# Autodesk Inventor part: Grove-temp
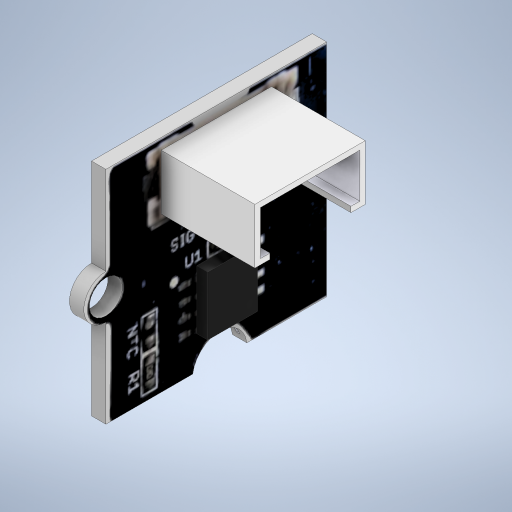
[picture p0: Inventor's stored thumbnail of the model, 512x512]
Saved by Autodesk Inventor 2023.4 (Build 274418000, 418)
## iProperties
Created: 2022-12
Part Number: Grove-temp
Material: Générique
Document SubType Name: Modeling
Designer: ecuenot
Density: 1 g/cm^3
Appearance: Par défaut
Author: ecuenot
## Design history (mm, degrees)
sketch "Esquisse1"
  geometry: L1 (20, 0)-(20, -20); L2 (0, -20)-(0, 0); L3 (11.5, 0)-(12, 0); L4 (10, 0)-(8, 0); L5 (0, 0)-(8, 0); L6 (11.5, 0)-(20, 0); L7 (20, -20)-(12, -20); L8 (8, -20)-(0, -20); C1 r 1.5 at (10, -20); A1 r 2 centre (10, 0) between (12, 0) and (8, 0); A2 r 2 centre (10, -20) between (8, -20) and (12, -20); 2 further points
  constraints: 16 end point, 5 parallel, 4 point on circle, 3 centre point, 2 coincident, 2 horizontal, 2 perpendicular, 1 horizontal alignment, 2 other
  dimensions: "d0" = 20 distance of L1.end L2.start; "d1" = 20 distance of L1.start L1.end
extrude "Extrusion1" new body sketch "Esquisse1" distance "d9" = 1.3; taper "d10" = 0 deg
sketch "Esquisse6"
  geometry: L1 (20, 20)-(0, 20) reference; L2 (15, 14)-(5, 14); L3 (5, 14)-(5, 19); L4 (5, 19)-(15, 19); L5 (15, 19)-(15, 14); L6 (15, 14)-(5, 19); L7 (5, 14)-(15, 19); 2 further points
  constraints: 12 end point, 2 midpoint, 2 parallel, 1 horizontal, 1 perpendicular
  dimensions: "d36" = 10 distance of L3.end L4.end; "d37" = 5 distance of L2.end L3.end
extrude "Extrusion4" join sketch "Esquisse6" distance "d38" = 8.5; taper "d39" = 0 deg
feature "Coque2" dims "d41" = 0.5
sketch "Esquisse7"
  geometry: L1 (3.749, 1.295)-(8.801, 1.295); L2 (8.801, 1.295)-(8.801, 8.634); L3 (8.801, 8.634)-(3.749, 8.634); L4 (3.749, 8.634)-(3.749, 1.295); L5 (3.749, 1.295)-(8.801, 8.634); L6 (8.801, 1.295)-(3.749, 8.634); 1 further point
  constraints: 12 end point, 2 parallel, 1 horizontal, 1 perpendicular
extrude "Extrusion5" cut sketch "Esquisse7" stored distance "d44" = 8.5; taper "d45" = 0 deg
sketch "Esquisse8" dims "d52" = 10
  geometry: L1 (-4.5, 7.064)-(-14.5, 7.064) reference; C1 r 0.5 at (-12.533, 4.536); C2 r 0.5 at (-10.533, 4.536); C3 r 0.5 at (-8.533, 4.536); C4 r 0.5 at (-6.533, 4.536); 1 further point
  constraints: 4 centre point, 1 horizontal, 6 other
  dimensions: "d46" = 1 diameter of C1; "d49" = 2 distance of C1.centre C2.centre
extrude "Extrusion6" join sketch "Esquisse8" distance "d54" = 7; taper "d55" = 0 deg
fillet "Congé2" dims "d56" = 0.5
sketch "Esquisse11"
  geometry: L1 (0, 0)-(20, 0) reference; C1 r 2.474 at (10.322, -0.327); 2 further points
  constraints: 1 centre point
extrude "Extrusion7" cut sketch "Esquisse11" distance "d73" = 7; taper "d74" = 0 deg
sketch "Esquisse12"
  geometry: L1 (12.727, 8.321)-(8.23, 8.321); L2 (8.23, 8.321)-(8.23, 2.989); L3 (8.23, 2.989)-(12.727, 2.989); L4 (12.727, 2.989)-(12.727, 8.321); 1 further point
  constraints: 8 end point, 2 parallel, 1 horizontal, 1 perpendicular
extrude "Extrusion8" join sketch "Esquisse12" distance "d75" = 1; taper "d76" = 0 deg
sketch "Esquisse15"
  geometry: L1 (-17.164, 54.007)-(43.478, 54.007); L2 (43.478, 54.007)-(43.478, -26.803); L3 (43.478, -26.803)-(-17.164, -26.803); L4 (-17.164, -26.803)-(-17.164, 54.007); 1 further point; 1 other entity
  constraints: 2 other
feature "Décalcomanie6" sketch "Esquisse15"
sketch "Esquisse16"
  geometry: L1 (-20, 20)-(0, 20) reference; L2 (-20, 20)-(-0.043, 20.043); L3 (-0.043, 20.043)-(0, 0); L4 (0, 0)-(-19.957, -0.043); L5 (-19.957, -0.043)-(-20, 20); 1 further point; 1 other entity
  constraints: 1 coincident, 2 other
feature "Décalcomanie7" sketch "Esquisse16"
node "Solide1"
node "Image8"
node "Image9"
